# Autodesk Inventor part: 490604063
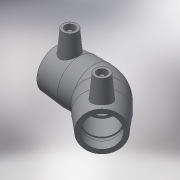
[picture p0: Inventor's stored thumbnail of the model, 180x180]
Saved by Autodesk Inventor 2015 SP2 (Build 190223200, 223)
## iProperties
Created: 2017-06
Part Number: 490604063
Material: Generic
Description: PLASSON 45° ELBOW 63
Document SubType Name: Modeling
Designer: KIM
Mass: 55.0731 g
Surface Area: 148.067 cm^2
Volume: 55.0731 cm^3
Density: 1 g/cm^3
Appearance: Default
Author: KIM
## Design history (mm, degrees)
derived "490604.ipt"
feature "Solid1::490604.ipt"
tag "TaggingFeature1"
body "Solid1"
other parameters: "d2" = 81, "d4" = 37, "d5" = 72.9, "d8" = 168 deg, "d10" = 22.8, "d11" = 7.6, "d14" = 17.6296, "d18" = 63, "d19" = 3.52592, "d20" = 168 deg, "d22" = 74.52, "d23" = 81, "d24" = 72.2844, "d29" = 59, "d30" = 15, "d31" = 59.2, "d34" = 5 deg, "d35" = 12, "d39" = 0, "d41" = 4, "d42" = 14, "d43" = 0, "d44" = 9.6, "d45" = 4.8, "d46" = 6, "d47" = 0, "d49" = 63, "d50" = 53.55, "d51" = 22.8, "d52" = 57, "d54" = 135 deg, "d65" = 63, "d67" = 45 deg, "d71" = 135 deg, "d75" = 4.05, "d82" = 45 deg, "d83" = 57, "d84" = 72.9, "d86" = 36.45, "d87" = 135 deg, "d88" = 148, "d90" = 57, "d91" = 0, "d92" = 57, "d93" = 0, "d94" = 135 deg, "d95" = 37.26, "d98" = 148, "d99" = 44.4, "d101" = 3, "d102" = 0, "d103" = 3, "d104" = 0, "d105" = 16.53, "d106" = 4.1325, "d_" = 63, "L_" = 148, "L_1" = 57, "D_" = 81, "A_" = 59, "d_2" = 12
